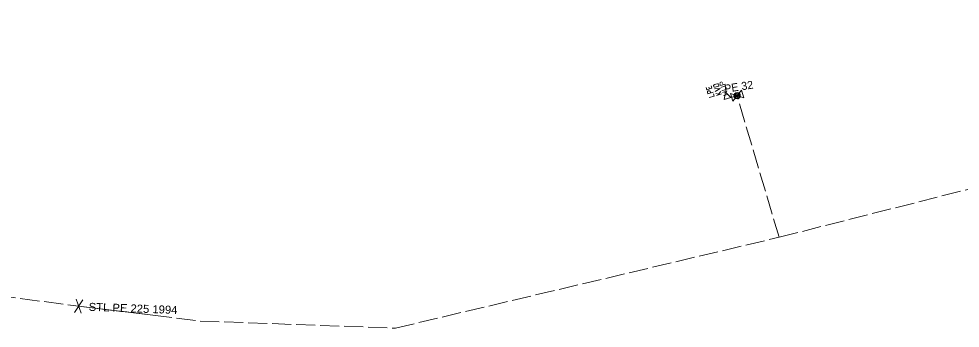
# Model space of a CAD drawing. Extents: x -688140 to -687678, y -1056859 to -1056384.
# Drawn here: x -687851.2 to -687762.9, y -1056675.2 to -1056646.2 of the extents above; entities that cross this region are included whole.
import ezdxf
from ezdxf.enums import TextEntityAlignment as Align

# ---------------------------------------------------------------- set-up
doc = ezdxf.new("R2010")
doc.units = 0
doc.header["$LTSCALE"] = 0.3
doc.linetypes.add('LONG_DASHED', pattern=[7.5, 6, -1.5])
for name, color, linetype, lineweight in [('13', 7, 'Continuous', 13), ('25', 7, 'Continuous', 13), ('40', 7, 'LONG_DASHED', 13), ('50', 7, 'LONG_DASHED', 13)]:
    doc.layers.add(name, color=color, linetype=linetype, lineweight=lineweight)
doc.layers.add('15', color=7, linetype='Continuous')

msp = doc.modelspace()

# ---------------------------------------------------------------- linework, layer by layer
at = {"layer": '13'}
for p, q in [((-687786.494, -1056652.599), (-687786.448, -1056652.752)), ((-687786.393, -1056652.975), (-687786.347, -1056653.129)), ((-687785.992, -1056652.356), (-687785.695, -1056652.268)), ((-687785.624, -1056652.508), (-687785.921, -1056652.596)), ((-687785.611, -1056653.255), (-687785.372, -1056653.007)), ((-687784.263, -1056653.914), (-687783.437, -1056652.866)), ((-687783.218, -1056653.604), (-687783.437, -1056652.866)), ((-687785.488, -1056653.281), (-687785.843, -1056653.177)), ((-687785.786, -1056653.369), (-687785.306, -1056653.227)), ((-687784.482, -1056653.176), (-687783.218, -1056653.604)), ((-687784.263, -1056653.914), (-687784.482, -1056653.176)), ((-687783.85, -1056653.39), (-687784.454, -1056653.569)), ((-687845.802, -1056672.43), (-687845.336, -1056673.77)), ((-687845.177, -1056672.51), (-687845.961, -1056673.69))]:
    msp.add_line(p, q, dxfattribs=at)
for points in [[(-687786.76, -1056652.615), (-687786.698, -1056652.826), (-687786.218, -1056652.684), (-687786.286, -1056652.454)], [(-687786.632, -1056653.046), (-687786.627, -1056652.993), (-687786.562, -1056652.932), (-687786.524, -1056652.92), (-687786.426, -1056652.933), (-687786.393, -1056652.975)], [(-687785.921, -1056652.596), (-687785.95, -1056652.604), (-687785.984, -1056652.594), (-687786.024, -1056652.564), (-687786.036, -1056652.525), (-687786.05, -1056652.477), (-687786.058, -1056652.449), (-687786.031, -1056652.399), (-687786.018, -1056652.374), (-687785.992, -1056652.356)], [(-687785.894, -1056653.005), (-687785.454, -1056652.729), (-687785.968, -1056652.756)], [(-687785.624, -1056652.508), (-687785.585, -1056652.496), (-687785.572, -1056652.471), (-687785.555, -1056652.425), (-687785.556, -1056652.383), (-687785.571, -1056652.335), (-687785.579, -1056652.307), (-687785.629, -1056652.28), (-687785.654, -1056652.266), (-687785.695, -1056652.268)], [(-687786.107, -1056653.058), (-687786.587, -1056653.2), (-687786.632, -1056653.046)], [(-687786.476, -1056653.574), (-687785.997, -1056653.432), (-687786.062, -1056653.211)]]:
    msp.add_lwpolyline(points, dxfattribs=at)
msp.add_lwpolyline([(-687784.454, -1056653.569), (-687784.94, -1056653.056), (-687785.068, -1056653.751)], close=True, dxfattribs=at)
for radius in [0.297, 0.223, 0.223, 0.112]:
    msp.add_circle((-687783.85, -1056653.39), radius, dxfattribs=at)
at = {"layer": '25'}
msp.add_line((-687845.569, -1056673.1), (-687838.621, -1056673.948), dxfattribs=at)
at = {"layer": '40'}
for points in [[(-687779.92, -1056666.65), (-687738.91, -1056656.24), (-687737.4, -1056653.49), (-687733.19, -1056652.96), (-687714.955, -1056647.461), (-687712.087, -1056646.581), (-687710.742, -1056646.192)], [(-687939.04, -1056649.24), (-687929.81, -1056651.84), (-687927.47, -1056652.38), (-687924.109, -1056653.23), (-687912.608, -1056656.651), (-687912.579, -1056656.66), (-687900.888, -1056660.13), (-687899.74, -1056660.29), (-687892.25, -1056664.99), (-687891.55, -1056665.45), (-687880.399, -1056667.31), (-687879.74, -1056667.45), (-687874.499, -1056668.398), (-687868.52, -1056669.48), (-687867.61, -1056669.65), (-687853.26, -1056672.09), (-687845.569, -1056673.1), (-687838.621, -1056673.948), (-687834.18, -1056674.49), (-687815.87, -1056675.16), (-687779.92, -1056666.65)]]:
    msp.add_lwpolyline(points, dxfattribs=at)
at = {"layer": '50'}
msp.add_line((-687779.92, -1056666.65), (-687783.85, -1056653.39), dxfattribs=at)

# ---------------------------------------------------------------- texts
at = {"layer": '13', "width": 0.9}
msp.add_text('HUP', height=0.5, rotation=106.507, dxfattribs=at).set_placement((-687784.853, -1056652.644), align=Align.CENTER)
at = {"layer": '15'}
msp.add_text('PE 32', height=0.75, rotation=8.84, dxfattribs=at).set_placement((-687784.997, -1056653.129))
at = {"layer": '15', "width": 1.05}
msp.add_text('STL PE 225 1994', height=0.75, rotation=357.904, dxfattribs=at).set_placement((-687844.627, -1056673.531))

doc.saveas('drawing.dxf')
